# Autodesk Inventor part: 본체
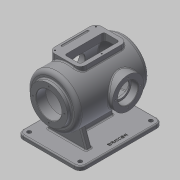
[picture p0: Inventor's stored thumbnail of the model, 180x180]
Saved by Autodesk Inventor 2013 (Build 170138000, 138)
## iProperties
Created: 2016-02
Part Number: 본체
Material: 일반
Document SubType Name: Modeling
Designer: mduedu
Density: 2.71 g/cm^3
Author: mduedu
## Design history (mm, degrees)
sketch "스케치2"
  geometry: L1 (0, 100)-(0, -100); L2 (65, -75.993)-(65, 100); L3 (65, 100)-(0, 100); A1 r 100 centre (0, 0) between (0, -100) and (65, -75.993); 2 further points
  constraints: 6 end point, 2 midpoint, 2 point on circle, 1 centre point, 1 coincident, 1 horizontal, 1 parallel, 1 vertical
  dimensions: "d3" = 200 distance of L1.start L1.end; "d5" = 130 diameter of L2 L1; "d6" = 100 radius of A1
revolve "회전1" sketch "스케치2" stored, may be unused: angle "d7" = 90 deg
sketch "스케치3"
  geometry: C1 r 47.5 at (0, 0); 1 further point
  constraints: 1 centre point, 1 coincident
  dimensions: "d8" = 95 diameter of C1
extrude "돌출2" join sketch "스케치3" distance "d10" = 10; taper "d11" = 0 deg
sketch "스케치5"
  geometry: L1 (47.5, 110)-(47.5, 100) reference; L2 (47.5, 100)-(65, 100) reference; L3 (65, 100)-(65, -75.993) reference; L4 (-65, -75.993)-(-65, 100) reference; L5 (-65, 100)-(-47.5, 100) reference; L6 (-47.5, 100)-(-47.5, 110) reference; L7 (-47.5, 110)-(47.5, 110) reference; L8 (55, 85)-(55, -71.239); L9 (0, 85)-(55, 85); L10 (0, 85)-(0, -90); A1 r 100 centre (0, 0) between (0, -100) and (65, -75.993) reference; A2 r 100 centre (0, 0) between (-65, -75.993) and (0, -100) reference; A3 r 90 centre (0, 0) between (0, -90) and (55, -71.239); 1 further point
  constraints: 6 end point, 2 point on circle, 1 centre point, 1 parallel, 1 perpendicular, 1 point on line, 1 vertical
  dimensions: "d13" = 10 distance between parallel lines of L3 L8; "d14" = 10 radial gap between concentric circles of A3 A1; "d15" = 15 distance between parallel lines of L9 L2
revolve "회전2" sketch "스케치5" stored, may be unused: angle "d16" = 90 deg
hole "구멍1" diameter "d19" = 65; stored, may be unused: countersink angle "d23" = 90 deg, drill point angle "d25" = 118 deg; dims "d17" = 10, "d18" = 10, "d20" = 6, "d21" = 4, "d22" = 2, "d24" = 8
node "작업 평면1"
sketch "스케치6"
  geometry: L1 (47.5, 110)-(-47.5, 110) reference; C1 r 40 at (0, -17); 1 further point
  constraints: 1 centre point, 1 vertical alignment
  dimensions: "d27" = 80 diameter of C1; "d29" = 127 distance from line of C1.centre L1
extrude "돌출3" join sketch "스케치6" stored distance "d30" = 10; taper "d31" = 0 deg
hole "구멍2" diameter "d34" = 42; stored, may be unused: countersink angle "d38" = 90 deg, drill point angle "d40" = 118 deg; dims "d32" = 10, "d33" = 10, "d35" = 6, "d36" = 52, "d37" = 18, "d39" = 8
sketch "스케치7" dims "d41" = 65
  geometry: C1 r 40 at (0, 0) reference; 3 further points
  constraints: 2 vertical alignment, 1 coincident, 2 other
hole "구멍3" sketch "스케치7" at (0, 32.5) diameter "d43" = 3.242; stored, may be unused: countersink angle "d47" = 90 deg, drill point angle "d49" = 118 deg; dims "d44" = 11, "d45" = 13, "d46" = 18, "d48" = 13
sketch "스케치8" dims "d53" = 80
  geometry: 3 further points
  constraints: 2 vertical alignment, 1 coincident, 2 other
hole "구멍4" sketch "스케치8" at (0, 40) diameter "d56" = 3.242; stored, may be unused: countersink angle "d60" = 90 deg, drill point angle "d62" = 118 deg; dims "d57" = 11, "d58" = 13, "d59" = 18, "d61" = 13
fillet "모깎기1" dims "d66" = 10
fillet "모깎기2" dims "d67" = 3
fillet "모깎기3" dims "d68" = 0.3
chamfer "모따기1" distance "d69" = 1; stored, may be unused: second distance "d70" = 2, angle "d71" = 45 deg
node "작업 평면5"
sketch "스케치10"
  geometry: L1 (-50, 0)-(50, 0); L2 (-50, 64)-(50, 64); L3 (50, 64)-(50, 50); L4 (50, 50)-(-50, 50); L5 (-50, 50)-(-50, 64); 3 further points
  constraints: 10 end point, 2 horizontal, 2 midpoint, 2 vertical, 1 coincident, 1 vertical alignment
  dimensions: "d132" = 100 distance of L1.start L1.end; "d158" = 50 distance between parallel lines of L4 L1; "d159" = 14 distance of L2.end L3.end; "d160" = 100 distance of L2.start L2.end
extrude "돌출5" join sketch "스케치10" stored distance "d84" = 10; taper "d85" = 0 deg
feature "면 기울기3" dims angle "d135" = 20 deg
sketch "스케치11"
  geometry: L1 (-100, 64)-(-100, 50) reference; L2 (-100, 50)-(-100, -50); L3 (-65, 90)-(-65, -71.239) reference; L4 (-100, -50)-(-65, -50); L5 (-100, 50)-(-55.515, 50) reference; 1 further point
  constraints: 4 end point, 1 collinear, 1 perpendicular, 1 point on line
  dimensions: "d161" = 100 distance between parallel lines of L4 L5
feature "리브1" sketch "스케치11" dims "d88" = 1, "d89" = 8, "d90" = 0, "d91" = 0, "d92" = 1, "d93" = 1
fillet "모깎기5" dims "d103" = 3
fillet "모깎기6" dims "d105" = 3
node "작업 평면6"
sketch "스케치15"
  geometry: L1 (-30, 60)-(50, 60); L2 (50, 60)-(50, -60); L3 (50, -60)-(-30, -60); L4 (-30, -60)-(-30, 60); 3 further points
  constraints: 8 end point, 2 parallel, 1 horizontal, 1 horizontal alignment, 1 midpoint, 1 perpendicular, 1 vertical alignment
  dimensions: "d110" = 80 distance of L2.end L3.end; "d112" = 60 distance from line of L3 point (10, 0); "d113" = 120 distance of L1.end L2.end; "d149" = 30 distance from line of L4 point (0, 0)
extrude "돌출8" join sketch "스케치15" stored distance "d114" = 10; taper "d115" = 0 deg
fillet "모깎기7" dims "d116" = 15
sketch "스케치16"
  geometry: L1 (-30, -45)-(-30, 45) reference; L2 (-15, 60)-(35, 60) reference; L3 (35, -60)-(-15, -60) reference; L4 (-20, -45)-(-20, 45); L5 (-15, 50)-(15, 50); L6 (20, 45)-(20, -45); L7 (15, -50)-(-15, -50); L8 (50, 45)-(50, -45) reference; A1 r 15 centre (-15, -45) between (-30, -45) and (-15, -60) reference; A2 r 15 centre (-15, 45) between (-15, 60) and (-30, 45) reference; A3 r 5 centre (-15, -45) between (-20, -45) and (-15, -50); A4 r 5 centre (-15, 45) between (-15, 50) and (-20, 45); A5 r 5 centre (15, 45) between (20, 45) and (15, 50); A6 r 5 centre (15, -45) between (15, -50) and (20, -45); A7 r 15 centre (35, 45) between (50, 45) and (35, 60) reference; A8 r 15 centre (35, -45) between (35, -60) and (50, -45) reference
  constraints: 8 end point, 8 point on circle, 4 centre point, 2 equal radius, 3 other
  dimensions: "d137" = 10 distance between parallel lines of L4 L1; "d150" = 40 distance between parallel lines of L6 L4; "d151" = 100 distance between parallel lines of L7 L5
extrude "돌출9" cut sketch "스케치16" stored distance "d118" = 10; taper "d119" = 0 deg
fillet "모깎기8" dims "d120" = 3
sketch "스케치17"
  geometry: L1 (-30, -45)-(-30, 45) reference; L2 (-20, 45)-(-20, -45) reference; L3 (-15, -50)-(15, -50) reference; L4 (20, -45)-(20, 45) reference; L5 (15, 50)-(-15, 50) reference; L6 (-15, 60)-(35, 60) reference; L7 (35, -60)-(-15, -60) reference; L8 (15, 55)-(-15, 55); L9 (-25, 45)-(-25, -45); L10 (-15, -55)-(15, -55); L11 (25, -45)-(25, 45); L12 (50, 45)-(50, -45) reference; L13 (35, 55)-(-15, 55); L14 (-25, 45)-(-25, -45); L15 (-15, -55)-(35, -55); L16 (45, -45)-(45, 45); A1 r 5 centre (-15, 45) between (-15, 50) and (-20, 45) reference; A2 r 5 centre (-15, -45) between (-20, -45) and (-15, -50) reference; A3 r 5 centre (15, -45) between (15, -50) and (20, -45) reference; A4 r 5 centre (15, 45) between (20, 45) and (15, 50) reference; A5 r 15 centre (-15, 45) between (-15, 60) and (-30, 45) reference; A6 r 15 centre (-15, -45) between (-30, -45) and (-15, -60) reference; A7 r 10 centre (-15, 45) between (-15, 55) and (-25, 45); A8 r 10 centre (-15, -45) between (-25, -45) and (-15, -55); A9 r 10 centre (15, -45) between (15, -55) and (25, -45); A10 r 10 centre (15, 45) between (25, 45) and (15, 55); A11 r 15 centre (35, 45) between (50, 45) and (35, 60) reference; A12 r 15 centre (35, -45) between (35, -60) and (50, -45) reference; A13 r 10 centre (-15, 45) between (-15, 55) and (-25, 45); A14 r 10 centre (-15, -45) between (-25, -45) and (-15, -55); A15 r 10 centre (35, -45) between (35, -55) and (45, -45); A16 r 10 centre (35, 45) between (45, 45) and (35, 55); 6 further points
  constraints: 18 point on circle, 16 end point, 8 centre point, 4 midpoint, 4 tangent, 11 other
  dimensions: "d138" = 5 distance between parallel lines of L8 L6; "d157" = 5 distance between parallel lines of L12 L16
hole "구멍5" sketch "스케치17" at (-25, 0), (42.071, 52.071), (42.071, -52.071) diameter "d122" = 3.242; stored, may be unused: countersink angle "d126" = 90 deg, drill point angle "d128" = 118 deg; dims "d123" = 9, "d124" = 13, "d125" = 18, "d127" = 11
sketch "스케치19"
  geometry: L1 (-50, 70)-(-35, 70) reference; L2 (-50, 42.603)-(-50, 70) reference; C1 r 2.5 at (-43, 70); 1 further point
  constraints: 1 centre point, 1 point on line
  dimensions: "d152" = 5 diameter of C1; "d153" = 7 distance from line of C1.centre L2
extrude "돌출11" cut sketch "스케치19" stored distance "d154" = 70; taper "d155" = 0 deg
fillet "모깎기11" dims "d156" = 2.5
sketch "스케치20"
  geometry: L1 (-80, 110)-(80, 110); L2 (80, 110)-(80, -100); L3 (80, -100)-(-80, -100); L4 (-80, -100)-(-80, 110); 2 further points
  constraints: 8 end point, 2 parallel, 1 horizontal, 1 midpoint, 1 perpendicular, 1 vertical alignment
  dimensions: "d162" = 160 distance of L1.start L1.end; "d164" = 210 distance of L1.end L2.end; "d165" = 110 distance from line of L1 point (0, 0)
extrude "돌출12" join sketch "스케치20" distance "d166" = 10; taper "d167" = 0 deg
fillet "모깎기12" dims "d168" = 15
fillet "모깎기13" dims "d169" = 3
fillet "모깎기14" dims "d170" = 3
sketch "스케치21"
  geometry: C1 r 5 at (-65, -95); C2 r 5 at (65, -95); C3 r 5 at (65, 85); C4 r 5 at (-65, 85); A1 r 15 centre (-65, -95) between (-80, -95) and (-65, -110) reference; A2 r 15 centre (-65, 85) between (-65, 100) and (-80, 85) reference; A3 r 15 centre (65, 85) between (80, 85) and (65, 100) reference; A4 r 15 centre (65, -95) between (65, -110) and (80, -95) reference; 1 further point
  constraints: 4 centre point, 4 coincident, 3 equal radius
  dimensions: "d171" = 10 diameter of C1
extrude "돌출13" cut sketch "스케치21" stored distance "d172" = 10; taper "d173" = 0 deg
sketch "스케치22"
  geometry: L1 (80, -95)-(80, 85) reference; 2 further points
  constraints: 1 horizontal alignment, 1 other
  dimensions: "d174" = 15 distance from line of L1 point (65, 0)
feature "엠보싱2" sketch "스케치22" dims "d13" = 10, "d175" = 0.5, "d176" = 0
node "솔리드2"
pattern_circular "원형 패턴1" dims angle "d51" = 360 deg
mirror "대칭1"
pattern_circular "원형 패턴2" dims angle "d64" = 360 deg
node "절단 모서리 투영1"
node "절단 모서리 투영2"
node "절단 모서리 투영3"
other parameters: "d26" = 75
